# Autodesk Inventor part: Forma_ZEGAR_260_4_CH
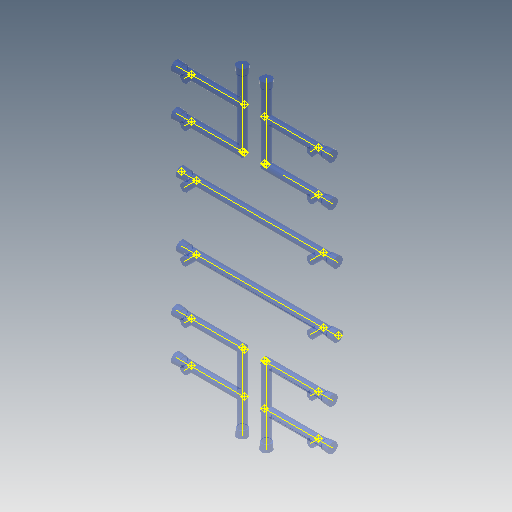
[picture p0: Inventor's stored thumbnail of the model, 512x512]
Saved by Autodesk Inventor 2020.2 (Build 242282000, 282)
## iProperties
Created: 2015-01
Part Number: Forma_ZEGAR_260_4_CH
Material: Ogólny
Document SubType Name: Modeling
Designer: F.Stasiak
Density: 1 g/cm^3
Appearance: Przezroczysty - niebieski
Catalog Web Link: www.expertbooks.pl
Manager: www.cadconsulting.pl
Company: Fabian Stasiak CAD Consulting
Author: F.Stasiak
Subject: Zbiór ćwiczeń. Autodesk Inventor 2020. Kurs Professional
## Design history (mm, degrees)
node "Płaszczyzna konstrukcyjna1"
node "Segment chłodzenia1"
  sketch "Szkic1"
    geometry: L1 (0, 0)-(0, -5.177); L2 (0, -5.177)-(6.924, -4.745); L3 (6.924, -4.745)-(6.924, -4); L4 (6.924, -4)-(149.076, -4); L5 (149.076, -4)-(149.076, -4.745); L6 (149.076, -4.745)-(156, -5.177); L7 (156, -5.177)-(156, 0); L8 (0, 0)-(156, 0)
    constraints: 16 end point, 4 perpendicular, 1 parallel
    dimensions: "d0" = 4 distance between parallel lines of L4 L8; "d1" = 6.92404 distance between parallel lines of L3 L1; "d2" = 6.92404 distance between parallel lines of L5 L7; "d3" = 93.5763 deg angle of L2 L3; "d4" = 0.74472 distance of L2.end L3.end; "d5" = 93.5763 deg angle of L6 L5; "d6" = 0.74472 distance of L4.end L5.end
  node "Punkt konstrukcyjny1"
  node "Oś konstrukcyjna1"
node "Płaszczyzna konstrukcyjna33"
node "Segment chłodzenia33"
  sketch "Szkic33"
    geometry: L1 (0, 0)-(0, -5.177); L2 (0, -5.177)-(6.924, -4.745); L3 (6.924, -4.745)-(6.924, -4); L4 (6.924, -4)-(68, -4); L5 (68, -4)-(70.403, 0); L6 (70.403, 0)-(68, 0); L7 (0, 0)-(68, 0)
    constraints: 14 end point, 2 perpendicular, 1 collinear, 1 parallel
    dimensions: "d184" = 4 distance between parallel lines of L4 L7; "d185" = 2.40344 distance of L5.end L6.end; "d186" = 6.92404 distance between parallel lines of L3 L1; "d187" = 93.5763 deg angle of L2 L3; "d188" = 0.74472 distance of L2.end L3.end; "d189" = 59 deg angle of L5 L7
  node "Punkt konstrukcyjny33"
  node "Oś konstrukcyjna33"
node "Płaszczyzna konstrukcyjna35"
node "Segment chłodzenia35"
  sketch "Szkic35"
    geometry: L1 (0, 0)-(0, -5.178); L2 (0, -5.178)-(6.924, -4.745); L3 (6.924, -4.745)-(6.924, -4); L4 (6.924, -4)-(68, -4); L5 (68, -4)-(70.403, 0); L6 (70.403, 0)-(68, 0); L7 (0, 0)-(68, 0)
    constraints: 14 end point, 2 perpendicular, 1 collinear, 1 parallel
    dimensions: "d200" = 4 distance between parallel lines of L4 L7; "d201" = 2.40344 distance of L5.end L6.end; "d202" = 6.924 distance between parallel lines of L3 L1; "d203" = 93.58 deg angle of L2 L3; "d204" = 0.7445 distance of L2.end L3.end; "d205" = 59 deg angle of L5 L7
  node "Punkt konstrukcyjny35"
  node "Oś konstrukcyjna35"
node "Płaszczyzna konstrukcyjna36"
node "Segment chłodzenia36"
  sketch "Szkic36"
    geometry: L1 (0, 0)-(0, -5.178); L2 (0, -5.178)-(6.924, -4.745); L3 (6.924, -4.745)-(6.924, -4); L4 (6.924, -4)-(75, -4); L5 (75, -4)-(77.403, 0); L6 (77.403, 0)-(75, 0); L7 (0, 0)-(75, 0)
    constraints: 14 end point, 2 perpendicular, 1 collinear, 1 parallel
    dimensions: "d208" = 4 distance between parallel lines of L4 L7; "d209" = 2.40344 distance of L5.end L6.end; "d210" = 6.924 distance between parallel lines of L3 L1; "d211" = 93.58 deg angle of L2 L3; "d212" = 0.7445 distance of L2.end L3.end; "d213" = 59 deg angle of L5 L7
  node "Punkt konstrukcyjny36"
  node "Oś konstrukcyjna36"
node "Płaszczyzna konstrukcyjna37"
node "Segment chłodzenia37"
  sketch "Szkic37"
    geometry: L1 (0, 0)-(0, -4); L2 (0, -4)-(7, -4); L3 (7, -4)-(9.403, 0); L4 (9.403, 0)-(7, 0); L5 (0, 0)-(7, 0)
    constraints: 10 end point, 1 collinear, 1 parallel, 1 perpendicular
    dimensions: "d216" = 4 distance between parallel lines of L2 L5; "d217" = 2.40344 distance of L3.end L4.end; "d218" = 59 deg angle of L3 L5
  node "Punkt konstrukcyjny37"
  node "Oś konstrukcyjna37"
node "Płaszczyzna konstrukcyjna38"
node "Segment chłodzenia38"
  sketch "Szkic38"
    geometry: L1 (0, 0)-(0, -4); L2 (0, -4)-(7, -4); L3 (7, -4)-(9.403, 0); L4 (9.403, 0)-(7, 0); L5 (0, 0)-(7, 0)
    constraints: 10 end point, 1 collinear, 1 parallel, 1 perpendicular
    dimensions: "d221" = 4 distance between parallel lines of L2 L5; "d222" = 2.40344 distance of L3.end L4.end; "d223" = 59 deg angle of L3 L5
  node "Punkt konstrukcyjny38"
  node "Oś konstrukcyjna38"
node "Płaszczyzna konstrukcyjna39"
node "Segment chłodzenia39"
  sketch "Szkic39"
    geometry: L1 (0, 0)-(0, -4); L2 (0, -4)-(12, -4); L3 (12, -4)-(14.403, 0); L4 (14.403, 0)-(12, 0); L5 (0, 0)-(12, 0)
    constraints: 10 end point, 1 collinear, 1 parallel, 1 perpendicular
    dimensions: "d226" = 4 distance between parallel lines of L2 L5; "d227" = 2.40344 distance of L3.end L4.end; "d228" = 59 deg angle of L3 L5
  node "Punkt konstrukcyjny39"
  node "Oś konstrukcyjna39"
node "Płaszczyzna konstrukcyjna40"
node "Segment chłodzenia40"
  sketch "Szkic40"
    geometry: L1 (0, 0)-(0, -4); L2 (0, -4)-(12, -4); L3 (12, -4)-(14.403, 0); L4 (14.403, 0)-(12, 0); L5 (0, 0)-(12, 0)
    constraints: 10 end point, 1 collinear, 1 parallel, 1 perpendicular
    dimensions: "d231" = 4 distance between parallel lines of L2 L5; "d232" = 2.40344 distance of L3.end L4.end; "d233" = 59 deg angle of L3 L5
  node "Punkt konstrukcyjny40"
  node "Oś konstrukcyjna40"
node "Płaszczyzna konstrukcyjna41"
node "Segment chłodzenia41"
  sketch "Szkic41"
    geometry: L1 (0, 0)-(0, -5.178); L2 (0, -5.178)-(6.924, -4.745); L3 (6.924, -4.745)-(6.924, -4); L4 (6.924, -4)-(68, -4); L5 (68, -4)-(70.403, 0); L6 (70.403, 0)-(68, 0); L7 (0, 0)-(68, 0)
    constraints: 14 end point, 2 perpendicular, 1 collinear, 1 parallel
    dimensions: "d236" = 4 distance between parallel lines of L4 L7; "d237" = 2.40344 distance of L5.end L6.end; "d238" = 6.924 distance between parallel lines of L3 L1; "d239" = 93.58 deg angle of L2 L3; "d240" = 0.7445 distance of L2.end L3.end; "d241" = 59 deg angle of L5 L7
  node "Punkt konstrukcyjny41"
  node "Oś konstrukcyjna41"
node "Płaszczyzna konstrukcyjna42"
node "Segment chłodzenia42"
  sketch "Szkic42"
    geometry: L1 (0, 0)-(0, -5.178); L2 (0, -5.178)-(6.924, -4.745); L3 (6.924, -4.745)-(6.924, -4); L4 (6.924, -4)-(68, -4); L5 (68, -4)-(70.403, 0); L6 (70.403, 0)-(68, 0); L7 (0, 0)-(68, 0)
    constraints: 14 end point, 2 perpendicular, 1 collinear, 1 parallel
    dimensions: "d244" = 4 distance between parallel lines of L4 L7; "d245" = 2.40344 distance of L5.end L6.end; "d246" = 6.924 distance between parallel lines of L3 L1; "d247" = 93.58 deg angle of L2 L3; "d248" = 0.7445 distance of L2.end L3.end; "d249" = 59 deg angle of L5 L7
  node "Punkt konstrukcyjny42"
  node "Oś konstrukcyjna42"
node "Płaszczyzna konstrukcyjna43"
node "Segment chłodzenia43"
  sketch "Szkic43"
    geometry: L1 (0, 0)-(0, -5.178); L2 (0, -5.178)-(6.924, -4.745); L3 (6.924, -4.745)-(6.924, -4); L4 (6.924, -4)-(75, -4); L5 (75, -4)-(77.403, 0); L6 (77.403, 0)-(75, 0); L7 (0, 0)-(75, 0)
    constraints: 14 end point, 2 perpendicular, 1 collinear, 1 parallel
    dimensions: "d252" = 4 distance between parallel lines of L4 L7; "d253" = 2.40344 distance of L5.end L6.end; "d254" = 6.924 distance between parallel lines of L3 L1; "d255" = 93.58 deg angle of L2 L3; "d256" = 0.7445 distance of L2.end L3.end; "d257" = 59 deg angle of L5 L7
  node "Punkt konstrukcyjny43"
  node "Oś konstrukcyjna43"
node "Płaszczyzna konstrukcyjna44"
node "Segment chłodzenia44"
  sketch "Szkic44"
    geometry: L1 (0, 0)-(0, -4); L2 (0, -4)-(7, -4); L3 (7, -4)-(9.403, 0); L4 (9.403, 0)-(7, 0); L5 (0, 0)-(7, 0)
    constraints: 10 end point, 1 collinear, 1 parallel, 1 perpendicular
    dimensions: "d260" = 4 distance between parallel lines of L2 L5; "d261" = 2.40344 distance of L3.end L4.end; "d262" = 59 deg angle of L3 L5
  node "Punkt konstrukcyjny44"
  node "Oś konstrukcyjna44"
node "Płaszczyzna konstrukcyjna45"
node "Segment chłodzenia45"
  sketch "Szkic45"
    geometry: L1 (0, 0)-(0, -4); L2 (0, -4)-(7, -4); L3 (7, -4)-(9.403, 0); L4 (9.403, 0)-(7, 0); L5 (0, 0)-(7, 0)
    constraints: 10 end point, 1 collinear, 1 parallel, 1 perpendicular
    dimensions: "d265" = 4 distance between parallel lines of L2 L5; "d266" = 2.40344 distance of L3.end L4.end; "d267" = 59 deg angle of L3 L5
  node "Punkt konstrukcyjny45"
  node "Oś konstrukcyjna45"
node "Płaszczyzna konstrukcyjna46"
node "Segment chłodzenia46"
  sketch "Szkic46"
    geometry: L1 (0, 0)-(0, -5.178); L2 (0, -5.178)-(6.924, -4.745); L3 (6.924, -4.745)-(6.924, -4); L4 (6.924, -4)-(149.076, -4); L5 (149.076, -4)-(149.076, -4.745); L6 (149.076, -4.745)-(156, -5.178); L7 (156, -5.178)-(156, 0); L8 (0, 0)-(156, 0)
    constraints: 16 end point, 4 perpendicular, 1 parallel
    dimensions: "d270" = 4 distance between parallel lines of L4 L8; "d271" = 6.924 distance between parallel lines of L3 L1; "d272" = 6.924 distance between parallel lines of L5 L7; "d273" = 93.58 deg angle of L2 L3; "d274" = 0.7445 distance of L2.end L3.end; "d275" = 93.58 deg angle of L6 L5; "d276" = 0.7445 distance of L4.end L5.end
  node "Punkt konstrukcyjny46"
  node "Oś konstrukcyjna46"
node "Płaszczyzna konstrukcyjna47"
node "Segment chłodzenia47"
  sketch "Szkic47"
    geometry: L1 (0, 0)-(0, -5.178); L2 (0, -5.178)-(6.924, -4.745); L3 (6.924, -4.745)-(6.924, -4); L4 (6.924, -4)-(68, -4); L5 (68, -4)-(68, 0); L6 (0, 0)-(68, 0)
    constraints: 12 end point, 3 perpendicular, 1 parallel
    dimensions: "d279" = 4 distance between parallel lines of L4 L6; "d280" = 6.924 distance between parallel lines of L3 L1; "d281" = 93.58 deg angle of L2 L3; "d282" = 0.7445 distance of L2.end L3.end
  node "Punkt konstrukcyjny47"
  node "Oś konstrukcyjna47"
node "Płaszczyzna konstrukcyjna48"
node "Segment chłodzenia48"
  sketch "Szkic48"
    geometry: L1 (0, 0)-(0, -5.178); L2 (0, -5.178)-(6.924, -4.745); L3 (6.924, -4.745)-(6.924, -4); L4 (6.924, -4)-(68, -4); L5 (68, -4)-(68, 0); L6 (0, 0)-(68, 0)
    constraints: 12 end point, 3 perpendicular, 1 parallel
    dimensions: "d285" = 4 distance between parallel lines of L4 L6; "d286" = 6.924 distance between parallel lines of L3 L1; "d287" = 93.58 deg angle of L2 L3; "d288" = 0.7445 distance of L2.end L3.end
  node "Punkt konstrukcyjny48"
  node "Oś konstrukcyjna48"
node "Płaszczyzna konstrukcyjna49"
node "Segment chłodzenia49"
  sketch "Szkic49"
    geometry: L1 (0, 0)-(0, -5.178); L2 (0, -5.178)-(6.924, -4.744); L3 (6.924, -4.744)-(6.924, -4); L4 (6.924, -4)-(68, -4); L5 (68, -4)-(68, 0); L6 (0, 0)-(68, 0)
    constraints: 12 end point, 3 perpendicular, 1 parallel
    dimensions: "d291" = 4 distance between parallel lines of L4 L6; "d292" = 6.924 distance between parallel lines of L3 L1; "d293" = 93.58 deg angle of L2 L3; "d294" = 0.7445 distance of L2.end L3.end
  node "Punkt konstrukcyjny49"
  node "Oś konstrukcyjna49"
node "Płaszczyzna konstrukcyjna50"
node "Segment chłodzenia50"
  sketch "Szkic50"
    geometry: L1 (0, 0)-(0, -5.178); L2 (0, -5.178)-(6.924, -4.744); L3 (6.924, -4.744)-(6.924, -4); L4 (6.924, -4)-(68, -4); L5 (68, -4)-(68, 0); L6 (0, 0)-(68, 0)
    constraints: 12 end point, 3 perpendicular, 1 parallel
    dimensions: "d297" = 4 distance between parallel lines of L4 L6; "d298" = 6.924 distance between parallel lines of L3 L1; "d299" = 93.58 deg angle of L2 L3; "d300" = 0.7445 distance of L2.end L3.end
  node "Punkt konstrukcyjny50"
  node "Oś konstrukcyjna50"
node "Płaszczyzna konstrukcyjna51"
node "Segment chłodzenia51"
  sketch "Szkic51"
    geometry: L1 (0, 0)-(0, -5.178); L2 (0, -5.178)-(6.924, -4.745); L3 (6.924, -4.745)-(6.924, -4); L4 (6.924, -4)-(75, -4); L5 (75, -4)-(75, 0); L6 (0, 0)-(75, 0)
    constraints: 12 end point, 3 perpendicular, 1 parallel
    dimensions: "d303" = 4 distance between parallel lines of L4 L6; "d304" = 6.924 distance between parallel lines of L3 L1; "d305" = 93.58 deg angle of L2 L3; "d306" = 0.7445 distance of L2.end L3.end
  node "Punkt konstrukcyjny51"
  node "Oś konstrukcyjna51"
node "Płaszczyzna konstrukcyjna52"
node "Segment chłodzenia52"
  sketch "Szkic52"
    geometry: L1 (0, 0)-(0, -5.178); L2 (0, -5.178)-(6.924, -4.745); L3 (6.924, -4.745)-(6.924, -4); L4 (6.924, -4)-(75, -4); L5 (75, -4)-(75, 0); L6 (0, 0)-(75, 0)
    constraints: 12 end point, 3 perpendicular, 1 parallel
    dimensions: "d309" = 4 distance between parallel lines of L4 L6; "d310" = 6.924 distance between parallel lines of L3 L1; "d311" = 93.58 deg angle of L2 L3; "d312" = 0.7445 distance of L2.end L3.end
  node "Punkt konstrukcyjny52"
  node "Oś konstrukcyjna52"
node "Płaszczyzna konstrukcyjna53"
node "Segment chłodzenia53"
  sketch "Szkic53"
    geometry: L1 (0, 0)-(0, -4); L2 (0, -4)-(12, -4); L3 (12, -4)-(12, 0); L4 (0, 0)-(12, 0)
    constraints: 8 end point, 2 perpendicular, 1 parallel
    dimensions: "d315" = 4 distance between parallel lines of L2 L4
  node "Punkt konstrukcyjny53"
  node "Oś konstrukcyjna53"
node "Płaszczyzna konstrukcyjna54"
node "Segment chłodzenia54"
  sketch "Szkic54"
    geometry: L1 (0, 0)-(0, -4); L2 (0, -4)-(7, -4); L3 (7, -4)-(7, 0); L4 (0, 0)-(7, 0)
    constraints: 8 end point, 2 perpendicular, 1 parallel
    dimensions: "d318" = 4 distance between parallel lines of L2 L4
  node "Punkt konstrukcyjny54"
  node "Oś konstrukcyjna54"
node "Płaszczyzna konstrukcyjna55"
node "Segment chłodzenia55"
  sketch "Szkic55"
    geometry: L1 (0, 0)-(0, -4); L2 (0, -4)-(7, -4); L3 (7, -4)-(7, 0); L4 (0, 0)-(7, 0)
    constraints: 8 end point, 2 perpendicular, 1 parallel
    dimensions: "d321" = 4 distance between parallel lines of L2 L4
  node "Punkt konstrukcyjny55"
  node "Oś konstrukcyjna55"
node "Płaszczyzna konstrukcyjna56"
node "Segment chłodzenia56"
  sketch "Szkic56"
    geometry: L1 (0, 0)-(0, -4); L2 (0, -4)-(12, -4); L3 (12, -4)-(12, 0); L4 (0, 0)-(12, 0)
    constraints: 8 end point, 2 perpendicular, 1 parallel
    dimensions: "d324" = 4 distance between parallel lines of L2 L4
  node "Punkt konstrukcyjny56"
  node "Oś konstrukcyjna56"
node "Płaszczyzna konstrukcyjna57"
node "Segment chłodzenia57"
  sketch "Szkic57"
    geometry: L1 (0, 0)-(0, -4); L2 (0, -4)-(7, -4); L3 (7, -4)-(7, 0); L4 (0, 0)-(7, 0)
    constraints: 8 end point, 2 perpendicular, 1 parallel
    dimensions: "d327" = 4 distance between parallel lines of L2 L4
  node "Punkt konstrukcyjny57"
  node "Oś konstrukcyjna57"
node "Płaszczyzna konstrukcyjna58"
node "Segment chłodzenia58"
  sketch "Szkic58"
    geometry: L1 (0, 0)-(0, -4); L2 (0, -4)-(7, -4); L3 (7, -4)-(7, 0); L4 (0, 0)-(7, 0)
    constraints: 8 end point, 2 perpendicular, 1 parallel
    dimensions: "d330" = 4 distance between parallel lines of L2 L4
  node "Punkt konstrukcyjny58"
  node "Oś konstrukcyjna58"
node "Bryła1"
revolve "Obrót1" stored, may be unused: angle "d7" = 0 deg
body "Srf1"
revolve "Obrót33" stored, may be unused: angle "d190" = 0 deg
body "Srf33"
revolve "Obrót35" stored, may be unused: angle "d206" = 0 deg
body "Srf35"
revolve "Obrót36" stored, may be unused: angle "d214" = 0 deg
body "Srf36"
revolve "Obrót37" stored, may be unused: angle "d219" = 0 deg
body "Srf37"
revolve "Obrót38" stored, may be unused: angle "d224" = 0 deg
body "Srf38"
revolve "Obrót39" stored, may be unused: angle "d229" = 0 deg
body "Srf39"
revolve "Obrót40" stored, may be unused: angle "d234" = 0 deg
body "Srf40"
revolve "Obrót41" stored, may be unused: angle "d242" = 0 deg
body "Srf41"
revolve "Obrót42" stored, may be unused: angle "d250" = 0 deg
body "Srf42"
revolve "Obrót43" stored, may be unused: angle "d258" = 0 deg
body "Srf43"
revolve "Obrót44" stored, may be unused: angle "d263" = 0 deg
body "Srf44"
revolve "Obrót45" stored, may be unused: angle "d268" = 0 deg
body "Srf45"
revolve "Obrót46" stored, may be unused: angle "d277" = 0 deg
body "Srf46"
revolve "Obrót47" stored, may be unused: angle "d283" = 0 deg
body "Srf47"
revolve "Obrót48" stored, may be unused: angle "d289" = 0 deg
body "Srf48"
revolve "Obrót49" stored, may be unused: angle "d295" = 0 deg
body "Srf49"
revolve "Obrót50" stored, may be unused: angle "d301" = 0 deg
body "Srf50"
revolve "Obrót51" stored, may be unused: angle "d307" = 0 deg
body "Srf51"
revolve "Obrót52" stored, may be unused: angle "d313" = 0 deg
body "Srf52"
revolve "Obrót53" stored, may be unused: angle "d316" = 0 deg
body "Srf53"
revolve "Obrót54" stored, may be unused: angle "d319" = 0 deg
body "Srf54"
revolve "Obrót55" stored, may be unused: angle "d322" = 0 deg
body "Srf55"
revolve "Obrót56" stored, may be unused: angle "d325" = 0 deg
body "Srf56"
revolve "Obrót57" stored, may be unused: angle "d328" = 0 deg
body "Srf57"
revolve "Obrót58" stored, may be unused: angle "d331" = 0 deg
body "Srf58"
feature "PowObrotowa1" dims angle "d8" = 0 deg
feature "PowObrotowa33" dims angle "d191" = 0 deg
feature "PowObrotowa35" dims angle "d207" = 0 deg
feature "PowObrotowa36" dims angle "d215" = 0 deg
feature "PowObrotowa37" dims angle "d220" = 0 deg
feature "PowObrotowa38" dims angle "d225" = 0 deg
feature "PowObrotowa39" dims angle "d230" = 0 deg
feature "PowObrotowa40" dims angle "d235" = 0 deg
feature "PowObrotowa41" dims angle "d243" = 0 deg
feature "PowObrotowa42" dims angle "d251" = 0 deg
feature "PowObrotowa43" dims angle "d259" = 0 deg
feature "PowObrotowa44" dims angle "d264" = 0 deg
feature "PowObrotowa45" dims angle "d269" = 0 deg
feature "PowObrotowa46" dims angle "d278" = 0 deg
feature "PowObrotowa47" dims angle "d284" = 0 deg
feature "PowObrotowa48" dims angle "d290" = 0 deg
feature "PowObrotowa49" dims angle "d296" = 0 deg
feature "PowObrotowa50" dims angle "d302" = 0 deg
feature "PowObrotowa51" dims angle "d308" = 0 deg
feature "PowObrotowa52" dims angle "d314" = 0 deg
feature "PowObrotowa53" dims angle "d317" = 0 deg
feature "PowObrotowa54" dims angle "d320" = 0 deg
feature "PowObrotowa55" dims angle "d323" = 0 deg
feature "PowObrotowa56" dims angle "d326" = 0 deg
feature "PowObrotowa57" dims angle "d329" = 0 deg
feature "PowObrotowa58" dims angle "d332" = 0 deg
